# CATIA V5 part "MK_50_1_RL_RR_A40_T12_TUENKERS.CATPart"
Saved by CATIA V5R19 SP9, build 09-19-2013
Part number: MK_50_1_RL_RR_A40_T12_TUENKERS
Material "MISCHDICHTE": density 4765 kg/m3, Young's modulus 2e+11 Pa, Poisson ratio 0.266
Bounding box of the stored display mesh (mm): x -173.5 to 150.266, y -118.5 to 144, z -119.161 to 119.161
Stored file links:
  G:\Konstruktion\Modelle\Catia_V5\MK_50_1_RL_RR_A40_T12_TUENKERS.CATPart
  G:\Konstruktion\Modelle\Catia_V5\Spannarme\SPANNARM_KPL_50_A40_242838_TUENKERS.CATPart
  C:\Catia\Tuenkers_B19SP9HF86_64\win_b64\reffiles\standard\MetricThickPitch.txt
  G:\Konstruktion\Modelle\Catia_V5\V2_50_1_BR3_ZL_ZR_RL_RR_A40_T12_TUENKERS.CATPart
  G:\Konstruktion\Modelle\Catia_V5\Handhebel\HANDHEBEL_KPL_50_63_TUENKERS.CATPart
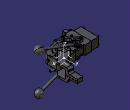
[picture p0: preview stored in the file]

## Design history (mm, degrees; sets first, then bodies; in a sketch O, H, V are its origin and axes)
AxisSystem1: origin (0, 0, 0), X (1, 0, 0), Y (0, 1, 0), Z (0, 0, 1)
Body1 (main body)
  Body2 "*DIT1\\*DIT8\\PartBody ( *SOL6 - wsp HANDHEBEL -  )"
    Solid1 "Solid.1": solid without history
  Assemble1: tool Body2
  Body3 "*DIT1\\*DIT9\\PartBody ( *SOL3 - wsp T 12 ABFRAGE -  )"
    Solid2 "Solid.1": solid without history
  Assemble2: tool Body3
  Body4 "*DIT1\\*DIT9\\Body.9 ( *SOL4 - wsp T 12 ABFRAGE -  )"
    Solid3 "Solid.1": solid without history
  Assemble3: tool Body4
  Body5 "*DIT1\\*DIT9\\Body.10 ( *SOL5 - wsp T 12 ABFRAGE -  )"
    Solid4 "Solid.1": solid without history
  Assemble4: tool Body5
  Body6 "*DIT1\\*DIT10\\*DIT17\\PartBody ( *SOL17 - wsp DREHBOLZEN -  )"
    Solid5 "Solid.1": solid without history
  Assemble5: tool Body6
  Body7 "*DIT1\\*DIT10\\*DIT18\\PartBody ( *SOL18 - wsp STOESSEL -  )"
    Solid6 "Solid.1": solid without history
  Assemble6: tool Body7
  Body8 "*DIT1\\*DIT10\\MK_MK2_50_1_A10_A11_A12_T12_081112_3D_xSET3_1.1\\PartBody ( *SOL13 - wsp GEHAEUSE -  )"
    Solid7 "Solid.1": solid without history
  Assemble7: tool Body8
  Body9 "*DIT1\\MK_MK2_50_1_A10_A11_A12_T12_081112_3D_xSET2.1\\PartBody ( *SOL1 - wsp MK_MK2 50_1 -  -Non Smart-  )"
    Solid8 "Solid.1": solid without history
  Assemble8: tool Body9
  Body10 "*DIT1\\MK_MK2_50_1_A10_A11_A12_T12_081112_3D_xSET2.1\\Body.2 ( *SOL2 - wsp MK_MK2 50_1 -  -Non Smart-  )"
    Solid9 "Solid.1": solid without history
  Assemble9: tool Body10
  Body11 "*DIT1\\MK_MK2_50_1_A10_A11_A12_T12_081112_3D_xSET2.1\\Body.3 ( *SOL24 - wsp MK_MK2 50_1 -  )"
    Solid10 "Solid.1": solid without history
  Assemble10: tool Body11
  Body12 "*DIT1\\MK_MK2_50_1_A10_A11_A12_T12_081112_3D_xSET2.1\\Body.4 ( *SOL25 - wsp MK_MK2 50_1 -  )"
    Solid11 "Solid.1": solid without history
  Assemble11: tool Body12
  Body13 "*DIT1\\MK_MK2_50_1_A10_A11_A12_T12_081112_3D_xSET2.1\\Body.5 ( *SOL26 - wsp MK_MK2 50_1 -  )"
    Solid12 "Solid.1": solid without history
  Assemble12: tool Body13
  Body14 "*DIT1\\MK_MK2_50_1_A10_A11_A12_T12_081112_3D_xSET2.1\\Body.6 ( *SOL27 - wsp MK_MK2 50_1 -  )"
    Solid13 "Solid.1": solid without history
  Assemble13: tool Body14
  Body15 "*DIT1\\MK_MK2_50_1_A10_A11_A12_T12_081112_3D_xSET2.1\\Body.7 ( *SOL28 - wsp MK_MK2 50_1 -  )"
    Solid14 "Solid.1": solid without history
  Assemble14: tool Body15
  Rotate1: Axis edge [XY plane of AxisSystem1 | ZX plane of AxisSystem1], Angle 90, ToTransfor Assemble14
Body16 "Spannarm_kpl_50_A40_242838_Tuenkers", material "Steel"
  Sketch1 on xy-plane, origin (0, 0, 0), H (1, 0, 0), V (0, 1, 0)
    line L1 (73, 144) -> (45, 144)
    arc A1 centre (53, 45.9289) radius 20 from (67.1421, 31.7868) to (73, 45.9289) ccw
    line L2 (67.1421, 31.7868) -> (17.6777, -17.6777)
    line L3 (9.5, 9.5) -> (9.5, -9.5)
    line L4 (9.5, 9.5) -> (-9.5, 9.5)
    line L5 (-17.6777, 17.6777) -> (-9.5, 9.5)
    line L6 (-0.0239, 35.3314) -> (-17.6777, 17.6777)
    line L7 (38.4202, 49.3239) -> (-0.0239, 35.3314)
    arc A2 centre (35, 58.7209) radius 10 from (38.4202, 49.3239) to (45, 58.7209) ccw
    line L8 (45, 58.7209) -> (45, 144)
    line L9 (73, 144) -> (73, 45.9289)
    line L10 (9.5, -9.5) -> (17.6777, -17.6777)
    point P13 (73, 37.6447)
    point P14 (45, 51.7188)
    reference intersected line E1 through (0, 0) direction (-1, 0)
    reference intersected line E2 through (0, 0) direction (0, 1)
    length L3 = 19
    length L4 = 19
    angle L5 L4 = 45
    angle L3 L10 = 45
    length L5 = 11.565
    length L10 = 11.565
    distance L2 L6 = 50
    angle L6 L7 = 25
    radius A2 = 10
    distance L3 L8 = 35.5
    distance L4 L1 = 134.5
    distance L8 L9 = 28
    radius A1 = 20
    distance P14 L4 = 42.2188
    distance L4 E1 = 9.5
    distance L3 E2 = 9.5
    tangency: A1 L2, L8 A2, A2 L7, L9 A1
    coincidence: L9 P13, L2 P13, L8 P14, L7 P14
    vertical: L3 V
    horizontal: L4 H
  Pad1: profile Sketch1, direction (0, 0, 1), length 34, mirrored extent
  Chamfer1: length 0.1, angle 45, on edge [start face of Pad1 | face of Pad1 from Sketch1.L3]; edge [start face of Pad1 | face of Pad1 from Sketch1.L4]; edge [face of Pad1 from Sketch1.L4 | end face of Pad1]; edge [face of Pad1 from Sketch1.L3 | end face of Pad1]
  Sketch2 on face of Pad1 from Sketch1.L9, origin (73, 0, 0), H (0, 1, 0), V (0, 0, 1)
    line L1 (144, -10) -> (144, 10)
    line L2 (103, 10) -> (144, 10)
    arc A1 centre (103, 18) radius 8 from (103, 10) to (95, 18) cw
    line L3 (95, 18) -> (95, 24)
    arc A2 centre (85, 24) radius 10 from (85, 34) to (95, 24) cw
    line L4 (-18, 34) -> (85, 34)
    line L5 (-18, 34) -> (-18, 24)
    line L6 (74, 24) -> (-18, 24)
    arc A3 centre (74, 18) radius 6 from (74, 24) to (80, 18) cw
    line L7 (80, 18) -> (80, -18)
    arc A4 centre (74, -18) radius 6 from (80, -18) to (74, -24) cw
    line L8 (-18, -24) -> (74, -24)
    line L9 (-18, -24) -> (-18, -34)
    line L10 (-18, -34) -> (85, -34)
    arc A5 centre (85, -24) radius 10 from (95, -24) to (85, -34) cw
    line L11 (95, -24) -> (95, -18)
    arc A6 centre (103, -18) radius 8 from (95, -18) to (103, -10) cw
    line L12 (103, -10) -> (144, -10)
    reference intersected line E1 through (0, 0) direction (-1, 0) from xy-plane
    reference intersected line E2 through (0, 0) direction (0, 1) from zx-plane
    reference intersected line E3 through (0, 0) direction (0, 1) from zx-plane
    reference intersected line E4 through (0, 0) direction (0, 1) from zx-plane
    line L13 (-23, -39) -> (149, -39)
    line L14 (149, -39) -> (149, 39)
    line L15 (149, 39) -> (-23, 39)
    line L16 (-23, 39) -> (-23, -39)
    reference intersected line E5 through (0, 0) direction (-1, 0) from xy-plane
    reference intersected line E6 through (0, 0) direction (0, 1) from zx-plane
    distance L12 E1 = 10
    distance L12 L2 = 20
    distance L4 L10 = 68
    distance L6 L8 = 48
    distance L10 L12 = 24
    distance L8 L10 = 10
    radius A3 = 6
    radius A4 = 6
    radius A5 = 10
    radius A2 = 10
    radius A1 = 8
    radius A6 = 8
    distance L7 E2 = 80
    distance L3 E3 = 95
    distance L1 L5 = 162
    distance E4 L1 = 144
    distance L16 L14 = 172
    distance L15 L13 = 78
    distance L13 E5 = 39
    distance L14 E6 = 149
    tangency: L6 A3, A3 L7, L7 A4, A4 L8, L10 A5, A5 L11, L3 A1, A1 L2, A6 L12, A2 L4, A2 L3, A6 L11
    vertical: L1 V, L14 V, L16 V
    horizontal: L12 H, L13 H, L15 H
    coincidence: L5 L9, L11 L3
  Pocket1: profile Sketch2, direction (-1, 0, 0), length 91
  Sketch3 on face of Pad1 from Sketch1.L9, origin (73, 131.0889, -0.3784), H (0, 1, 0), V (0, 0, 1)
    point P1 (3.9111, 0.3784)
    reference intersected line E1 through (0, 0.3784) direction (-1, 0) from xy-plane
    reference intersected line E2 through (-131.0889, 0) direction (0, 1) from zx-plane
    distance P1 E2 = 135
    coincidence: P1 E1
  Hole1: placed by Sketch3, at (73, 135, 0) direction (-1, 0, 0), diameter 6, through (limit type 6)
  Sketch4 on face of Pad1 from Sketch1.L9, origin (73, 113.9529, 0.5693), H (0, 1, 0), V (0, 0, 1)
    point P1 (-8.9529, -0.5693)
    reference projected point E1 (21.0471, -0.5693) from axis of face of Hole1
    reference intersected line E2 through (0, -0.5693) direction (-1, 0) from xy-plane
    distance P1 E1 = 30
    coincidence: P1 E2
  Hole2: placed by Sketch4, at (73, 105, 0) direction (-1, 0, 0), diameter 6, through (limit type 6)
  Sketch5 on face of Pad1 from Sketch1.L9, origin (73, 123.4122, -0.1089), H (0, 1, 0), V (0, 0, 1)
    point P1 (-3.4122, 0.1089)
    reference projected point E1 (11.5878, 0.1089) from axis of face of Hole1
    reference projected point E2 (-18.4122, 0.1089) from axis of face of Hole2
    distance P1 E1 = 15
    distance E2 P1 = 15
  Hole3: placed by Sketch5, at (73, 120, 0) direction (-1, 0, 0), diameter 9, through (limit type 6)
  Sketch6 on face of Pad1 from Sketch1.L9, origin (73, 93.5248, 1.4062), H (0, 1, 0), V (0, 0, 1)
    point P1 (-3.5248, -1.4062)
    reference projected point E1 (26.4752, -1.4062) from axis of face of Hole3
    reference projected point E2 (11.4752, -1.4062) from axis of face of Hole2
    distance P1 E1 = 30
    distance P1 E2 = 15
  Hole4: placed by Sketch6, at (73, 90, 0) direction (-1, 0, 0), diameter 9, through (limit type 6)
  Sketch7 on face of Pad1 from Sketch1.L10, origin (13.7879, -13.7879, 28.7565), H (0.7071, -0.7071, 0), V (0, 0, 1)
    point P1 (-1.4991, 0.2435)
    reference intersected line E1 through (0, -28.7565) direction (-1, 0) from xy-plane
    reference projected line E2 (-19.4991, -62.7565) -> (-19.4991, 5.2435) from edge [face of Pad1 from Sketch1.L3 | face of Pad1 from Sketch1.L4]
    distance P1 E1 = 29
    distance E2 P1 = 18
  Hole5: placed by Sketch7, at (12.7279, -12.7279, 29) direction (0.7071, 0.7071, 0), diameter 4.917, depth 16, V-bottom angle 120, threaded "M6", thread diameter 6, thread depth 14, pitch 1
  RectPattern1: of Hole5, direction 1 instances 2, spacing 58, along edge [face of Pad1 from Sketch1.L3 | face of Pad1 from Sketch1.L4] reversed, direction 2 instances 2, spacing 36, along edge [face of Pad1 from Sketch1.L10 | face of Pocket1] reversed
  Body17 "KLEMMFLANSCH KPL"
    Sketch8 on xy-plane, origin (0, 0, 0), H (1, 0, 0), V (0, 1, 0)
      line L1 (-18.3848, 15.5563) -> (-26.8771, 7.064)
      line L2 (-26.8771, 7.064) -> (-18.7454, -1.0677)
      line L3 (-18.7454, -1.0677) -> (-23.6951, -6.0175)
      line L4 (-23.6951, -6.0175) -> (-6.0175, -23.6951)
      line L5 (-6.0175, -23.6951) -> (-1.0677, -18.7454)
      line L6 (-1.0677, -18.7454) -> (7.064, -26.8771)
      line L7 (7.064, -26.8771) -> (16.9635, -16.9776)
      line L8 (16.9635, -16.9776) -> (9.3267, -9.3409)
      line L9 (9.3267, -9.3409) -> (-9.3409, -9.3409)
      point P10 (-9.3409, -9.3409)
      line L10 (-9.3409, -9.3409) -> (-9.3409, 6.5125)
      line L11 (-9.3409, 6.5125) -> (-18.3848, 15.5563)
      reference intersected line E1 through (0, 0) direction (-0.7071, -0.7071)
      reference intersected line E2 through (0, 0) direction (-0.7071, 0.7071)
      distance L4 L8 = 21
      angle L5 L6 = 90
      angle L9 L8 = 45
      distance L7 L5 = 11.5
      distance L5 L3 = 25
      distance L7 L1 = 48
      distance P10 L8 = 13.2
      distance P10 L5 = 12.5
      distance L4 L6 = 7
      angle L9 L10 = 90
      distance E2 L11 = 2
      distance L11 L8 = 1.99
      coincidence: L2 L6, E1 P10
    Pad2: profile Sketch8, direction (0, 0, 1), length 34, opposite side length -24
    Sketch9 on face of Pad2 from Sketch8.L6, origin (-9.9066, -9.9066, 0), H (0.7071, -0.7071, 0), V (0, 0, 1)
      circle A1 centre (18, 29) radius 5
      point P1 (18, 29)
      point P2 (18, 29)
      reference projected line E1 (12.5, 34) -> (24, 34) from edge [face of Pad2 from Sketch8.L6 | end face of Pad2]
      reference projected line E2 (24, 24) -> (24, 34) from edge [face of Pad2 from Sketch8.L7 | face of Pad2 from Sketch8.L6]
      radius A1 = 5
      distance E1 P2 = 5
      distance P2 E2 = 6
      coincidence: P2 P1
    Pad3: profile Sketch9, direction (-0.7071, -0.7071, 0), length 1.2
    RectPattern2: of Pad3, direction 1 instances 2, spacing 36, along edge [start face of Pad2 | face of Pad2 from Sketch8.L4] reversed
    Chamfer2: length 0.1, angle 45, on edge [face of Pad3 from Sketch9.A1 | end face of Pad3]; edge [face of RectPattern2 | face of RectPattern2]
    Sketch10 on face of Pad2 from Sketch8.L6, origin (-9.9066, -9.9066, 0), H (0.7071, -0.7071, 0), V (0, 0, 1)
      circle A1 centre (18, 29) radius 3
      point P1 (18, 29)
      reference projected line E1 (12.5, 24) -> (24, 24) from edge [start face of Pad2 | face of Pad2 from Sketch8.L6]
      reference projected line E2 (24, 24) -> (24, 34) from edge [face of Pad2 from Sketch8.L7 | face of Pad2 from Sketch8.L6]
      radius A1 = 3
      distance P1 E1 = 5
      distance E2 P1 = 6
    Pad4: profile Sketch10, direction (0.7071, 0.7071, 0), length 20
    RectPattern3: of Pad4, direction 1 instances 2, spacing 36, along edge [start face of Pad2 | face of Pad2 from Sketch8.L4] reversed
    Sketch11 on end face of Pad3, origin (-10.7551, -10.7551, 0), H (0.7071, -0.7071, 0), V (0, 0, 1)
      circle A1 centre (18, 29) radius 5
      point P1 (18, 29)
      circle A2 centre (-18, 29) radius 5
      point P2 (-18, 29)
      reference projected line E1 (-24, 24) -> (-12.5, 24) from edge [start face of Pad2 | face of Pad2 from Sketch8.L2]
      reference projected line E2 (12.5, 24) -> (24, 24) from edge [start face of Pad2 | face of Pad2 from Sketch8.L6]
      reference projected line E3 (24, 24) -> (24, 34) from edge [face of Pad2 from Sketch8.L7 | face of Pad2 from Sketch8.L6]
      reference projected line E4 (-24, 24) -> (-24, 34) from edge [face of Pad2 from Sketch8.L2 | face of Pad2 from Sketch8.L1]
      radius A1 = 5
      radius A2 = 5
      distance E1 P2 = 5
      distance E2 P1 = 5
      distance E3 P1 = 6
      distance E4 P2 = 6
    Pad5: profile Sketch11, direction (-0.7071, -0.7071, 0), length 6
    Fillet1: radius 0.5, on edge [face of Pad5 from Sketch11.A1 | end face of Pad5]; edge [face of Pad5 from Sketch11.A2 | end face of Pad5]
    Chamfer3: length 0.1, angle 45, on edge [face of Pad2 from Sketch8.L9 | end face of Pad2]; edge [face of Pad2 from Sketch8.L10 | end face of Pad2]
    Mirror1: of the body so far, about xy-plane
  Assemble15: tool Body17
Body18 "ENDLAGENRASTE_LINKS"
  Body19 "LUMP108"
    Solid15 "Manifold Solid #2147": solid without history
  Assemble16: tool Body19
  Body20 "LUMP109"
    Solid16 "Manifold Solid #2556": solid without history
  Assemble17: tool Body20
  Body21 "LUMP110"
    Solid17 "Manifold Solid #2941": solid without history
  Assemble18: tool Body21
  Body22 "LUMP111"
    Solid18 "Manifold Solid #3571": solid without history
  Assemble19: tool Body22
  Body23 "LUMP112"
    Solid19 "Manifold Solid #4879": solid without history
  Assemble20: tool Body23
  Body24 "LUMP114"
    Solid20 "Manifold Solid #6444": solid without history
  Assemble21: tool Body24
  Body25 "LUMP117"
    Solid21 "Manifold Solid #8121": solid without history
  Assemble22: tool Body25
  Body26 "LUMP118"
    Solid22 "Manifold Solid #9264": solid without history
  Assemble23: tool Body26
  Body27 "LUMP120"
    Solid23 "Manifold Solid #10792": solid without history
  Assemble24: tool Body27
  Body28 "LUMP122"
    Solid24 "Manifold Solid #11586": solid without history
  Assemble25: tool Body28
  Body29 "LUMP126"
    Solid25 "Manifold Solid #12918": solid without history
  Assemble26: tool Body29
  Body30 "LUMP127"
    Solid26 "Manifold Solid #13327": solid without history
  Assemble27: tool Body30
  Body31 "LUMP130"
    Solid27 "Manifold Solid #14250": solid without history
  Assemble28: tool Body31
  Body32 "LUMP132"
    Solid28 "Manifold Solid #15068": solid without history
  Assemble29: tool Body32
  Body33 "LUMP133"
    Solid29 "Manifold Solid #15325": solid without history
  Assemble30: tool Body33
  Body34 "LUMP134"
    Solid30 "Manifold Solid #15582": solid without history
  Assemble31: tool Body34
  Body35 "LUMP135"
    Solid31 "Manifold Solid #15839": solid without history
  Assemble32: tool Body35
  Body36 "LUMP124"
    Solid32 "Manifold Solid #12404": solid without history
  Assemble33: tool Body36
  Rotate2: Axis edge, Angle 90, ToTransfor Assemble33
Body37 "ENDLAGENRASTE_RECHTS"
  Solid33 "Manifold Solid #290": solid without history
  Body38 "LUMP105"
    Solid34 "Manifold Solid #920": solid without history
  Assemble34: tool Body38
  Body39 "LUMP106"
    Solid35 "Manifold Solid #1329": solid without history
  Assemble35: tool Body39
  Body40 "LUMP107"
    Solid36 "Manifold Solid #1738": solid without history
  Assemble36: tool Body40
  Body41 "LUMP113"
    Solid37 "Manifold Solid #6187": solid without history
  Assemble37: tool Body41
  Body42 "LUMP115"
    Solid38 "Manifold Solid #6701": solid without history
  Assemble38: tool Body42
  Body43 "LUMP116"
    Solid39 "Manifold Solid #7411": solid without history
  Assemble39: tool Body43
  Body44 "LUMP119"
    Solid40 "Manifold Solid #10407": solid without history
  Assemble40: tool Body44
  Body45 "LUMP121"
    Solid41 "Manifold Solid #11177": solid without history
  Assemble41: tool Body45
  Body46 "LUMP123"
    Solid42 "Manifold Solid #11995": solid without history
  Assemble42: tool Body46
  Body47 "LUMP124"
    Solid43 "Manifold Solid #12404": solid without history
    Symmetry1: Reference ZX plane of AxisSystem1, ToTransfor Solid43
  Assemble43: tool Body47
  Body48 "LUMP125"
    Solid44 "Manifold Solid #12661": solid without history
  Assemble44: tool Body48
  Body49 "LUMP128"
    Solid45 "Manifold Solid #13736": solid without history
  Assemble45: tool Body49
  Body50 "LUMP129"
    Solid46 "Manifold Solid #13993": solid without history
  Assemble46: tool Body50
  Body51 "LUMP131"
    Solid47 "Manifold Solid #14659": solid without history
  Assemble47: tool Body51
  Body52 "LUMP136"
    Solid48 "Manifold Solid #16096": solid without history
  Assemble48: tool Body52
  Rotate3: Axis edge, Angle 90, ToTransfor Assemble48
Body53 "Handhebel_KPL_218625_TUENKERS"
  Body54 "Mitnehmer"
    Sketch12 on yz-plane, origin (0, 0, 0), H (0, 1, 0), V (0, 0, 1)
      axis line L1 (0, 22.4174) -> (0, -4.8423)
      reference intersected line E1 through (0, 0) direction (0, 1) from zx-plane
      line L2 (0, 0) -> (16, 0)
      line L3 (16, 0) -> (16, 2)
      line L4 (12.49, 12) -> (0, 12)
      reference intersected line E2 through (0, 0) direction (-1, 0) from xy-plane
      reference intersected line E3 through (0, 0) direction (0, 1) from zx-plane
      arc A1 centre (0, 2) radius 16 from (16, 2) to (12.49, 12) ccw
      point P5 (0, 2)
      reference intersected line E4 through (0, 0) direction (-1, 0) from xy-plane
      reference intersected line E5 through (0, 0) direction (0, 1) from zx-plane
      distance L2 L4 = 12
      distance L3 E3 = 16
      radius A1 = 16
      distance E4 P5 = 2
      coincidence: L1 E1, L2 E2, E5 P5
    Shaft1: profile Sketch12, axis Sketch12.L1, angle 360
    Sketch13 on face of Shaft1 from Sketch12.L2, origin (0, 0, 0), H (1, 0, 0), V (0, -1, 0)
      line L1 (-1, 15.9687) -> (-1, 5.364)
      line L2 (-1, 5.364) -> (-6.364, 0)
      point P2 (-6.364, 0)
      line L3 (-6.364, 0) -> (-1, -5.364)
      line L4 (-1, -5.364) -> (-1, -15.9687)
      line L5 (1, -15.9687) -> (1, -5.364)
      line L6 (1, -5.364) -> (6.364, 0)
      point P5 (6.364, 0)
      line L7 (6.364, 0) -> (1, 5.364)
      line L8 (1, 5.364) -> (1, 15.9687)
      reference intersected line E1 through (0, 0) direction (1, 0) from zx-plane
      reference intersected line E2 through (0, 0) direction (1, 0) from zx-plane
      reference intersected line E3 through (0, 0) direction (0, 1) from yz-plane
      arc A1 centre (0, 0) radius 16 from (1, 15.9687) to (-1, 15.9687) ccw
      point P7 (0, 0)
      reference intersected line E4 through (0, 0) direction (1, 0) from zx-plane
      reference intersected line E5 through (0, 0) direction (0, 1) from yz-plane
      arc A2 centre (0, 0) radius 16 from (-1, -15.9687) to (1, -15.9687) ccw
      reference intersected line E6 through (0, 0) direction (1, 0) from zx-plane
      distance E3 L4 = 1
      distance L5 L4 = 2
      radius A1 = 16
      radius A2 = 16
      distance L3 L7 = 9
      distance L2 L6 = 9
      angle E6 L2 = 45
      distance P7 L2 = 4.5
      coincidence: P2 E1, P5 E2, L1 L4, L8 L5, P7 E4, P7 E5
    Pocket2: profile Sketch13, direction (0, 0, 1), length 12
    Sketch14 on face of Pocket2 from Sketch13.L4, origin (-1, 0, 0), H (0, 1, 0), V (0, 0, 1)
      circle A1 centre (10, 5) radius 2.1
      point P1 (10, 5)
      reference intersected line E1 through (0, 0) direction (-1, 0) from xy-plane
      reference intersected line E2 through (0, 0) direction (0, 1) from zx-plane
      distance E1 P1 = 5
      distance E2 P1 = 10
      radius A1 = 2.1
    Pocket3: profile Sketch14, direction (-1, 0, 0), length 16
    Sketch15, origin (7, 0, 0), H (0, 1, 0), V (0, 0, 1)
      circle A1 centre (10, 5) radius 4.5
      point P1 (10, 5)
      reference intersected line E1 through (0, 0) direction (-1, 0) from xy-plane
      reference intersected line E2 through (0, 0) direction (0, 1) from zx-plane
      radius A1 = 4.5
      distance E1 P1 = 5
      distance E2 P1 = 10
    Pocket4: profile Sketch15, direction (1, 0, 0), length 9
    Sketch16, origin (-7, 0, 0), H (0, 1, 0), V (0, 0, 1)
      circle A1 centre (-10, 5) radius 4.5
      point P1 (-10, 5)
      reference intersected line E1 through (0, 0) direction (0, 1) from zx-plane
      reference intersected line E2 through (0, 0) direction (-1, 0) from xy-plane
      radius A1 = 4.5
      distance E1 P1 = 10
      distance P1 E2 = 5
    Pocket5: profile Sketch16, direction (-1, 0, 0), length 9
    Sketch17, origin (7, 0, 0), H (0, 1, 0), V (0, 0, 1)
      circle A1 centre (10, 5) radius 4.25
      point P1 (10, 5)
      reference intersected line E1 through (0, 0) direction (0, 1) from zx-plane
      reference intersected line E2 through (0, 0) direction (-1, 0) from xy-plane
      distance E1 P1 = 10
      distance E2 P1 = 5
      radius A1 = 4.25
    Pad6: profile Sketch17, direction (1, 0, 0), length 5
    Fillet2: radius 0.5, on end face of Pad6
    Sketch18, origin (7, 0, 0), H (0, 1, 0), V (0, 0, 1)
      circle A1 centre (10, 5) radius 2.5
      point P1 (10, 5)
      reference intersected line E1 through (0, 0) direction (0, 1) from zx-plane
      reference intersected line E2 through (0, 0) direction (-1, 0) from xy-plane
      radius A1 = 2.5
      distance P1 E1 = 10
      distance E2 P1 = 5
    Pad7: profile Sketch18, direction (-1, 0, 0), length 15
    Sketch19 on face of Pocket2 from Sketch13.L8, origin (1, 0, 0), H (0, -1, 0), V (0, 0, 1)
      circle A1 centre (10, 5) radius 2.1
      point P1 (10, 5)
      reference intersected line E1 through (0, 0) direction (0, -1) from zx-plane
      reference intersected line E2 through (0, 0) direction (-1, 0) from xy-plane
      radius A1 = 2.1
      distance E1 P1 = 10
      distance E2 P1 = 5
    Pocket6: profile Sketch19, direction (1, 0, 0), length 16
    Sketch20, origin (-7, 0, 0), H (0, 1, 0), V (0, 0, 1)
      circle A1 centre (-10, 5) radius 4.25
      point P1 (-10, 5)
      reference intersected line E1 through (0, 0) direction (0, 1) from zx-plane
      reference intersected line E2 through (0, 0) direction (-1, 0) from xy-plane
      radius A1 = 4.25
      distance E1 P1 = 10
      distance E2 P1 = 5
    Pad8: profile Sketch20, direction (-1, 0, 0), length 5
    Fillet3: radius 0.5, on end face of Pad8
    Sketch21, origin (-7, 0, 0), H (0, 1, 0), V (0, 0, 1)
      circle A1 centre (-10, 5) radius 2.5
      point P1 (-10, 5)
      reference intersected line E1 through (0, 0) direction (0, 1) from zx-plane
      reference intersected line E2 through (0, 0) direction (-1, 0) from xy-plane
      radius A1 = 2.5
      distance P1 E1 = 10
      distance E2 P1 = 5
    Pad9: profile Sketch21, direction (1, 0, 0), length 15
  Assemble49: tool Body54
  Body55 "Griffstange"
    Sketch22, origin (16.0748, 0, 4.6157), H (0, 1, 0), V (-0.342, 0, 0.9397)
      circle A1 centre (0, 3.04) radius 6
      point P1 (0, 3.04)
      reference projected point E1 (0, 3.04)
      radius A1 = 6
      coincidence: P1 E1
    Pad10: profile Sketch22, direction (0.9397, 0, 0.342), length 178
  Assemble50: tool Body55
  Body56 "KU40B12M"
    Sketch23, origin (0, 0, 0), H (0, 0, 1), V (1, 0, 0)
      arc A1 centre (74.1663, 198.2751) radius 20 from (78.2522, 178.697) to (81.0067, 217.069) ccw
      point P1 (74.1663, 198.2751)
      line L1 (81.0067, 217.069) -> (68.3519, 182.3004)
      line L2 (68.3519, 182.3004) -> (78.2522, 178.697)
      reference projected line E1 (62.7138, 184.3525) -> (73.9901, 180.2482) from edge [face of Pad10 from Sketch22.A1 | end face of Pad10]
      reference projected line E2 (2, 0) -> (10.2085, 22.5526)
      radius A1 = 20
      distance P1 L2 = 17
      coincidence: L1 P1, L2 E1, L1 E2
      perpendicularity: L2 L1
    Shaft2: profile Sketch23, axis Sketch23.L1, angle 360
  Assemble51: tool Body56
  Translate1: ToTransfor Assemble51, Direction edge [ZX plane of AxisSystem1 | YZ plane of AxisSystem1], Length 25
  Translate2: ToTransfor Translate1, Direction edge [YZ plane of AxisSystem1 | XY plane of AxisSystem1], Length -4
  Translate3: ToTransfor Translate2, Direction edge [XY plane of AxisSystem1 | ZX plane of AxisSystem1], Length -68
Body57 "Handhebel_KPL_218625_TUENKERS"
  Body58 "Mitnehmer"
    Sketch24 on yz-plane, origin (0, 0, 0), H (0, 1, 0), V (0, 0, 1)
      axis line L1 (0, 22.4174) -> (0, -4.8423)
      reference intersected line E1 through (0, 0) direction (0, 1) from zx-plane
      line L2 (0, 0) -> (16, 0)
      line L3 (16, 0) -> (16, 2)
      line L4 (12.49, 12) -> (0, 12)
      reference intersected line E2 through (0, 0) direction (-1, 0) from xy-plane
      reference intersected line E3 through (0, 0) direction (0, 1) from zx-plane
      arc A1 centre (0, 2) radius 16 from (16, 2) to (12.49, 12) ccw
      point P5 (0, 2)
      reference intersected line E4 through (0, 0) direction (-1, 0) from xy-plane
      reference intersected line E5 through (0, 0) direction (0, 1) from zx-plane
      distance L2 L4 = 12
      distance L3 E3 = 16
      radius A1 = 16
      distance E4 P5 = 2
      coincidence: L1 E1, L2 E2, E5 P5
    Shaft3: profile Sketch24, axis Sketch24.L1, angle 360
    Sketch25 on face of Shaft3 from Sketch24.L2, origin (0, 0, 0), H (1, 0, 0), V (0, -1, 0)
      line L1 (-1, 15.9687) -> (-1, 5.364)
      line L2 (-1, 5.364) -> (-6.364, 0)
      point P2 (-6.364, 0)
      line L3 (-6.364, 0) -> (-1, -5.364)
      line L4 (-1, -5.364) -> (-1, -15.9687)
      line L5 (1, -15.9687) -> (1, -5.364)
      line L6 (1, -5.364) -> (6.364, 0)
      point P5 (6.364, 0)
      line L7 (6.364, 0) -> (1, 5.364)
      line L8 (1, 5.364) -> (1, 15.9687)
      reference intersected line E1 through (0, 0) direction (1, 0) from zx-plane
      reference intersected line E2 through (0, 0) direction (1, 0) from zx-plane
      reference intersected line E3 through (0, 0) direction (0, 1) from yz-plane
      arc A1 centre (0, 0) radius 16 from (1, 15.9687) to (-1, 15.9687) ccw
      point P7 (0, 0)
      reference intersected line E4 through (0, 0) direction (1, 0) from zx-plane
      reference intersected line E5 through (0, 0) direction (0, 1) from yz-plane
      arc A2 centre (0, 0) radius 16 from (-1, -15.9687) to (1, -15.9687) ccw
      reference intersected line E6 through (0, 0) direction (1, 0) from zx-plane
      distance E3 L4 = 1
      distance L5 L4 = 2
      radius A1 = 16
      radius A2 = 16
      distance L3 L7 = 9
      distance L2 L6 = 9
      angle E6 L2 = 45
      distance P7 L2 = 4.5
      coincidence: P2 E1, P5 E2, L1 L4, L8 L5, P7 E4, P7 E5
    Pocket7: profile Sketch25, direction (0, 0, 1), length 12
    Sketch26 on face of Pocket7 from Sketch25.L4, origin (-1, 0, 0), H (0, 1, 0), V (0, 0, 1)
      circle A1 centre (10, 5) radius 2.1
      point P1 (10, 5)
      reference intersected line E1 through (0, 0) direction (-1, 0) from xy-plane
      reference intersected line E2 through (0, 0) direction (0, 1) from zx-plane
      distance E1 P1 = 5
      distance E2 P1 = 10
      radius A1 = 2.1
    Pocket8: profile Sketch26, direction (-1, 0, 0), length 16
    Sketch27, origin (7, 0, 0), H (0, 1, 0), V (0, 0, 1)
      circle A1 centre (10, 5) radius 4.5
      point P1 (10, 5)
      reference intersected line E1 through (0, 0) direction (-1, 0) from xy-plane
      reference intersected line E2 through (0, 0) direction (0, 1) from zx-plane
      radius A1 = 4.5
      distance E1 P1 = 5
      distance E2 P1 = 10
    Pocket9: profile Sketch27, direction (1, 0, 0), length 9
    Sketch28, origin (-7, 0, 0), H (0, 1, 0), V (0, 0, 1)
      circle A1 centre (-10, 5) radius 4.5
      point P1 (-10, 5)
      reference intersected line E1 through (0, 0) direction (0, 1) from zx-plane
      reference intersected line E2 through (0, 0) direction (-1, 0) from xy-plane
      radius A1 = 4.5
      distance E1 P1 = 10
      distance P1 E2 = 5
    Pocket10: profile Sketch28, direction (-1, 0, 0), length 9
    Sketch29, origin (7, 0, 0), H (0, 1, 0), V (0, 0, 1)
      circle A1 centre (10, 5) radius 4.25
      point P1 (10, 5)
      reference intersected line E1 through (0, 0) direction (0, 1) from zx-plane
      reference intersected line E2 through (0, 0) direction (-1, 0) from xy-plane
      distance E1 P1 = 10
      distance E2 P1 = 5
      radius A1 = 4.25
    Pad11: profile Sketch29, direction (1, 0, 0), length 5
    Fillet4: radius 0.5, on end face of Pad11
    Sketch30, origin (7, 0, 0), H (0, 1, 0), V (0, 0, 1)
      circle A1 centre (10, 5) radius 2.5
      point P1 (10, 5)
      reference intersected line E1 through (0, 0) direction (0, 1) from zx-plane
      reference intersected line E2 through (0, 0) direction (-1, 0) from xy-plane
      radius A1 = 2.5
      distance P1 E1 = 10
      distance E2 P1 = 5
    Pad12: profile Sketch30, direction (-1, 0, 0), length 15
    Sketch31 on face of Pocket7 from Sketch25.L8, origin (1, 0, 0), H (0, -1, 0), V (0, 0, 1)
      circle A1 centre (10, 5) radius 2.1
      point P1 (10, 5)
      reference intersected line E1 through (0, 0) direction (0, -1) from zx-plane
      reference intersected line E2 through (0, 0) direction (-1, 0) from xy-plane
      radius A1 = 2.1
      distance E1 P1 = 10
      distance E2 P1 = 5
    Pocket11: profile Sketch31, direction (1, 0, 0), length 16
    Sketch32, origin (-7, 0, 0), H (0, 1, 0), V (0, 0, 1)
      circle A1 centre (-10, 5) radius 4.25
      point P1 (-10, 5)
      reference intersected line E1 through (0, 0) direction (0, 1) from zx-plane
      reference intersected line E2 through (0, 0) direction (-1, 0) from xy-plane
      radius A1 = 4.25
      distance E1 P1 = 10
      distance E2 P1 = 5
    Pad13: profile Sketch32, direction (-1, 0, 0), length 5
    Fillet5: radius 0.5, on end face of Pad13
    Sketch33, origin (-7, 0, 0), H (0, 1, 0), V (0, 0, 1)
      circle A1 centre (-10, 5) radius 2.5
      point P1 (-10, 5)
      reference intersected line E1 through (0, 0) direction (0, 1) from zx-plane
      reference intersected line E2 through (0, 0) direction (-1, 0) from xy-plane
      radius A1 = 2.5
      distance P1 E1 = 10
      distance E2 P1 = 5
    Pad14: profile Sketch33, direction (1, 0, 0), length 15
  Assemble52: tool Body58
  Body59 "Griffstange"
    Sketch34, origin (16.0748, 0, 4.6157), H (0, 1, 0), V (-0.342, 0, 0.9397)
      circle A1 centre (0, 3.04) radius 6
      point P1 (0, 3.04)
      reference projected point E1 (0, 3.04)
      radius A1 = 6
      coincidence: P1 E1
    Pad15: profile Sketch34, direction (0.9397, 0, 0.342), length 178
  Assemble53: tool Body59
  Body60 "KU40B12M"
    Sketch35, origin (0, 0, 0), H (0, 0, 1), V (1, 0, 0)
      arc A1 centre (74.1663, 198.2751) radius 20 from (78.2522, 178.697) to (81.0067, 217.069) ccw
      point P1 (74.1663, 198.2751)
      line L1 (81.0067, 217.069) -> (68.3519, 182.3004)
      line L2 (68.3519, 182.3004) -> (78.2522, 178.697)
      reference projected line E1 (62.7138, 184.3525) -> (73.9901, 180.2482) from edge [face of Pad15 from Sketch34.A1 | end face of Pad15]
      reference projected line E2 (2, 0) -> (10.2085, 22.5526)
      radius A1 = 20
      distance P1 L2 = 17
      coincidence: L1 P1, L2 E1, L1 E2
      perpendicularity: L2 L1
    Shaft4: profile Sketch35, axis Sketch35.L1, angle 360
  Assemble54: tool Body60
  Translate4: Direction edge [ZX plane of AxisSystem1 | YZ plane of AxisSystem1], Length 25, ToTransfor Assemble54
  Translate5: Direction edge [YZ plane of AxisSystem1 | XY plane of AxisSystem1], Length -4, ToTransfor Translate4
  Translate6: Direction edge [XY plane of AxisSystem1 | ZX plane of AxisSystem1], Length -68, ToTransfor Translate5
  Symmetry2: ToTransfor Translate6, Reference XY plane of AxisSystem1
